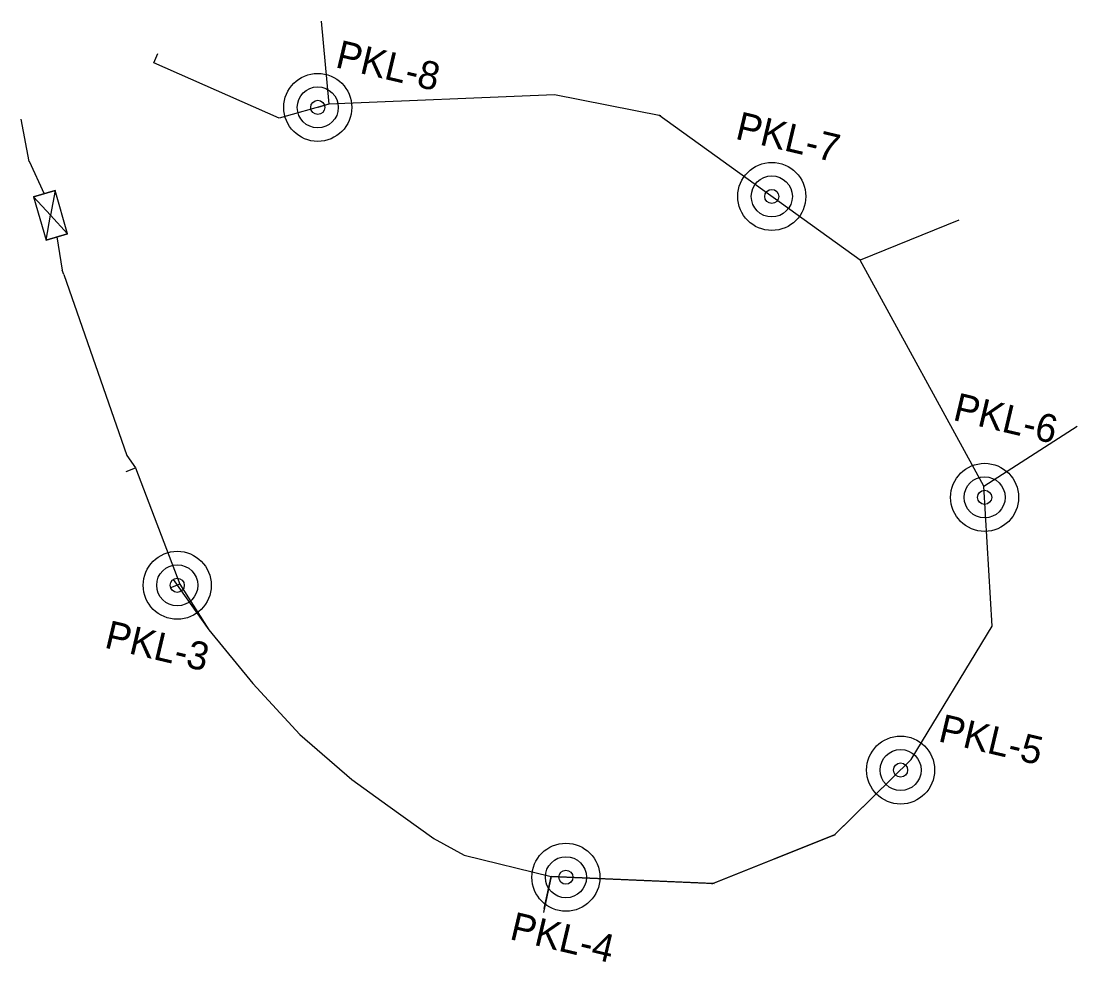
# Model space of a CAD drawing. Extents: x 0 to 511877, y 0 to 6211921.
# Drawn here: x 511607.53 to 511654.31, y 6211603.43 to 6211645.31 of the extents above; entities that cross this region are included whole.
import ezdxf

# ---------------------------------------------------------------- set-up
doc = ezdxf.new("R2010")
doc.units = 0
for name, color, linetype in [('Help', 7, 'Continuous'), ('TV_U_LYS_iWay', 7, 'Continuous'), ('TV_U_LYS_Ledn-', 7, 'Continuous'), ('TV_U_LYS_Mastenummer', 7, 'Continuous'), ('TV_U_LYS_Skab-', 7, 'Continuous')]:
    doc.layers.add(name, color=color, linetype=linetype)

msp = doc.modelspace()

# ---------------------------------------------------------------- linework, layer by layer
at = {"layer": 'Help'}
for points in [[(511620.888, 6211645.31), (511621.233, 6211641.606), (511619.026, 6211640.988), (511613.438, 6211643.446), (511613.619, 6211643.858)], [(511649.273, 6211636.451), (511644.886, 6211634.669), (511635.914, 6211641.127)], [(511650.751, 6211618.383), (511650.392, 6211624.611), (511654.538, 6211627.274)], [(511612.208, 6211625.269), (511612.628, 6211625.429), (511614.601, 6211620.242), (511614.18, 6211620.082)], [(511614.295, 6211620.46), (511615.881, 6211618.22), (511617.846, 6211615.832), (511619.932, 6211613.559), (511622.251, 6211611.559), (511623.856, 6211610.404)], [(511647.158, 6211612.445), (511643.735, 6211609.088), (511638.333, 6211606.925), (511631.127, 6211607.233), (511630.783, 6211605.632)], [(511630.822, 6211605.813), (511631.127, 6211607.233), (511638.387, 6211606.923)]]:
    msp.add_lwpolyline(points, dxfattribs=at)
at = {"layer": 'TV_U_LYS_iWay'}
for centre, radius in [((511620.738, 6211641.467), 1.514), ((511620.738, 6211641.467), 0.914), ((511620.738, 6211641.467), 0.314), ((511640.948, 6211637.504), 1.514), ((511640.948, 6211637.504), 0.914), ((511640.948, 6211637.504), 0.314), ((511650.421, 6211624.112), 1.514), ((511650.421, 6211624.112), 0.914), ((511650.421, 6211624.112), 0.314), ((511614.482, 6211620.197), 1.514), ((511614.482, 6211620.197), 0.914), ((511614.482, 6211620.197), 0.314), ((511646.681, 6211611.976), 1.514), ((511646.681, 6211611.976), 0.914), ((511646.681, 6211611.976), 0.314), ((511631.782, 6211607.205), 1.514), ((511631.782, 6211607.205), 0.914), ((511631.782, 6211607.205), 0.314)]:
    msp.add_circle(centre, radius, dxfattribs=at)
at = {"layer": 'TV_U_LYS_Ledn-'}
for p, q in [((511636.012, 6211641.085), (511631.272, 6211642.027)), ((511607.891, 6211639.053), (511607.528, 6211640.949)), ((511607.887, 6211639.069), (511608.564, 6211637.624)), ((511609.124, 6211635.704), (511609.364, 6211634.223)), ((511609.43, 6211634.034), (511609.364, 6211634.223)), ((511609.43, 6211634.034), (511612.235, 6211625.973)), ((511623.856, 6211610.404), (511625.898, 6211608.935)), ((511638.283, 6211606.905), (511643.781, 6211609.106)), ((511625.874, 6211608.95), (511627.248, 6211608.182))]:
    msp.add_line(p, q, dxfattribs=at)
for points in [[(511631.272, 6211642.027), (511621.233, 6211641.606), (511620.737, 6211641.467)], [(511650.392, 6211624.611), (511644.886, 6211634.669), (511635.914, 6211641.127)], [(511612.235, 6211625.973), (511612.628, 6211625.429), (511614.601, 6211620.242), (511614.601, 6211620.242)], [(511650.751, 6211618.383), (511650.392, 6211624.611)], [(511614.601, 6211620.242), (511615.881, 6211618.22), (511617.846, 6211615.832), (511619.932, 6211613.559), (511622.251, 6211611.559), (511623.856, 6211610.404)], [(511643.699, 6211609.053), (511647.158, 6211612.445), (511650.751, 6211618.383)], [(511627.248, 6211608.182), (511631.127, 6211607.233), (511638.387, 6211606.923)]]:
    msp.add_lwpolyline(points, dxfattribs=at)
at = {"layer": 'TV_U_LYS_Skab-'}
for points in [[(511609.044, 6211637.764), (511608.084, 6211637.484), (511608.644, 6211635.564), (511609.604, 6211635.844)], [(511609.044, 6211637.764), (511608.844, 6211636.664), (511608.084, 6211637.484)], [(511608.644, 6211635.564), (511608.844, 6211636.664), (511609.604, 6211635.844)]]:
    msp.add_lwpolyline(points, close=True, dxfattribs=at)

# ---------------------------------------------------------------- texts
at = {"layer": 'TV_U_LYS_Mastenummer'}
for s, p in [('PKL-8', (511621.474, 6211643.26)), ('PKL-7', (511639.278, 6211640.075)), ('PKL-6', (511648.963, 6211627.563)), ('PKL-3', (511611.196, 6211617.434)), ('PKL-5', (511648.31, 6211613.263)), ('PKL-4', (511629.232, 6211604.457))]:
    msp.add_text(s, height=1.25, rotation=346.664, dxfattribs=at).set_placement(p)

doc.saveas('drawing.dxf')
